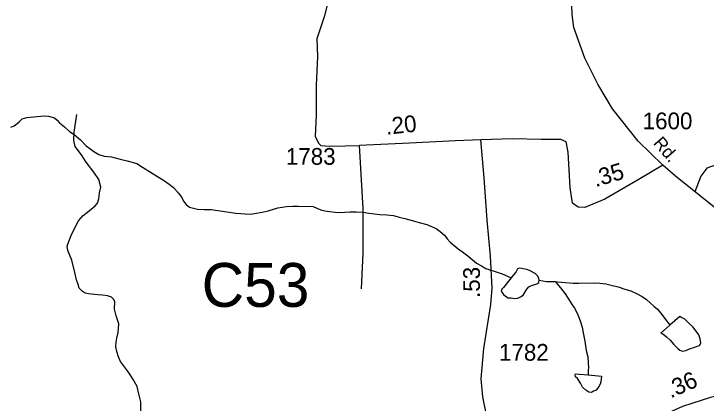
# Model space of a CAD drawing. Extents: x 2001466 to 2224147, y 644118 to 847247.
# Drawn here: x 2024898 to 2030071, y 729712 to 732621 of the extents above; entities that cross this region are included whole.
import ezdxf

# ---------------------------------------------------------------- set-up
doc = ezdxf.new("R2010")
doc.units = 0
for name, color, linetype in [('Exist Hydrographic Misc Water Feature', 7, 'Continuous'), ('Exist Road Non-System Type 51', 7, 'Continuous'), ('Exist Road Secondary Mileage Hundredths English Label', 7, 'Continuous'), ('Exist Road Secondary Structure Culvert Number Label', 7, 'Continuous'), ('Exist Road Secondary Type 51 Attributed', 7, 'Continuous'), ('Exist Road Secondary Type 51 Label', 7, 'Continuous'), ('Exist Road Secondary Type 51 Number Label', 7, 'Continuous')]:
    doc.layers.add(name, color=color, linetype=linetype)

msp = doc.modelspace()

# ---------------------------------------------------------------- linework, layer by layer
at = {"layer": 'Exist Hydrographic Misc Water Feature'}
for points in [[(2024874.8, 731774.2), (2024900.8, 731784.3), (2024922.7, 731802.7), (2024936.9, 731814.7), (2024960.7, 731836.4), (2024994.7, 731847.2), (2025072.6, 731855.4), (2025128.4, 731859.2), (2025156.5, 731857.8), (2025202.4, 731843.8), (2025220.7, 731827.8), (2025238.7, 731806.1), (2025276.9, 731775.8), (2025314.8, 731742.3), (2025349, 731718.6), (2025395.2, 731680.7), (2025437.4, 731634.8), (2025465.7, 731614.5), (2025495.7, 731592.6), (2025533.8, 731571.2), (2025573.8, 731557.3), (2025627.9, 731553.8), (2025691.9, 731536), (2025746, 731521.8), (2025771.9, 731515.5), (2025816.2, 731502.3), (2025858.2, 731476.1), (2025932.4, 731430.3), (2026024.7, 731373.4), (2026058.7, 731347.3), (2026090.9, 731323.6), (2026129.1, 731281), (2026153.3, 731249.4), (2026165.2, 731221.3), (2026185.3, 731195.4), (2026211.5, 731177.6), (2026239.4, 731168), (2026271.4, 731161.6), (2026319.4, 731159.9), (2026371.2, 731158.8), (2026489.5, 731140.8), (2026555.6, 731132.9), (2026593.7, 731129.7), (2026625.9, 731125.7), (2026665.7, 731123.3), (2026695.8, 731130), (2026753.7, 731140.3), (2026797.5, 731150.1), (2026871.6, 731170.7), (2026935.5, 731180.9), (2026983.5, 731184.8), (2027023.5, 731183.2), (2027133.6, 731181.8), (2027161.5, 731169.7), (2027191.9, 731156), (2027221.6, 731149.7), (2027255.6, 731144), (2027297.7, 731139.9), (2027334, 731136.7), (2027371.9, 731138.4), (2027409.6, 731140.9), (2027457.8, 731140.7), (2027507.8, 731138.9), (2027549.7, 731131.5)], [(2027549.7, 731131.5), (2027591.9, 731125.7), (2027633.7, 731121.6), (2027685.8, 731119.7), (2027735.9, 731113.7), (2027775.8, 731102.2), (2027818.3, 731090.7), (2027874.1, 731076.5), (2027926.3, 731063.1), (2027984.2, 731047.2), (2028054.3, 731017.8), (2028084.4, 730995.9), (2028116.4, 730967.4), (2028136.7, 730939.9), (2028158.9, 730915.6), (2028186.8, 730889.6), (2028219, 730864.4), (2028251.2, 730842.4), (2028291.1, 730812), (2028355.5, 730758.3), (2028391.4, 730737), (2028425.7, 730719), (2028509.7, 730691.1), (2028546, 730677.3), (2028585.8, 730661.6), (2028614.1, 730648.8)], [(2028823.9, 730631.4), (2028820, 730644.6), (2028812, 730660.3), (2028791.9, 730680.4), (2028749.6, 730704.2), (2028729.7, 730712), (2028703.9, 730715.8), (2028677.7, 730719.6), (2028661.9, 730715.9), (2028647.7, 730689.9), (2028619.8, 730656), (2028614.1, 730648.8)], [(2028614.1, 730648.8), (2028556.1, 730575.3), (2028544.2, 730563.3), (2028539.9, 730547.7), (2028556.5, 730523.6), (2028572.5, 730511.8), (2028592.6, 730499.9), (2028614.7, 730497.8), (2028638.5, 730494), (2028664.5, 730496), (2028684.6, 730506.2), (2028704.5, 730519.7), (2028718.3, 730544.1), (2028730.4, 730564.4), (2028746.1, 730580.4), (2028766.2, 730592.3), (2028790.2, 730598.4), (2028806.2, 730604.6), (2028820, 730614.2), (2028823.9, 730631.4)], [(2028823.9, 730631.4), (2028878, 730620.4), (2028912, 730620.6), (2028943.2, 730619.9)], [(2028943.2, 730619.9), (2028960, 730618.8), (2029020.1, 730613.4), (2029078.1, 730609.7), (2029118.3, 730608.1), (2029236.2, 730610.6), (2029276.2, 730608.2), (2029320.1, 730604.8), (2029362.1, 730594.9), (2029412.4, 730580.8), (2029464.2, 730564.9), (2029508.5, 730551.8), (2029550.8, 730531.2), (2029592.6, 730509.9), (2029624.8, 730486.3), (2029678.9, 730435.9), (2029707.2, 730414), (2029729.2, 730386.5), (2029755.4, 730354.8), (2029775.5, 730326.5), (2029787.6, 730312.3), (2029799.3, 730294)], [(2028943.2, 730619.9), (2028982.4, 730574.8), (2029016.4, 730529), (2029038.6, 730493.2), (2029065, 730453.4), (2029086.9, 730421.8), (2029105, 730389.4), (2029113, 730372), (2029129.4, 730327.4), (2029143.3, 730279.5), (2029151.7, 730237.5), (2029163.8, 730175.8), (2029174.3, 730105.8), (2029186.4, 730058), (2029188.6, 730012), (2029192.8, 729978.2), (2029188.6, 729957.9), (2029188.6, 729923.4)], [(2029799.3, 730294), (2029733.1, 730235.5), (2029748, 730230.2), (2029773.9, 730208.4), (2029802, 730182.4), (2029830.3, 730150.6), (2029858.1, 730120.6), (2029874.3, 730108.8), (2029894.2, 730101), (2029918.2, 730105.4), (2029954.5, 730119.4), (2029986.1, 730131.1), (2030004.1, 730137.3), (2030020.1, 730143.5), (2030030, 730161.4), (2030025.9, 730193.4), (2030015.6, 730221.5), (2029995.5, 730249), (2029971.7, 730281.5), (2029945.5, 730304.9), (2029925.4, 730325.1), (2029911.5, 730339.3), (2029897.3, 730347), (2029881.3, 730354.7), (2029873.5, 730359), (2029799.3, 730294)], [(2029188.6, 729923.4), (2029288.7, 729914), (2029283, 729872.3), (2029279.3, 729854.3), (2029269.2, 729836.4), (2029259.4, 729821.9), (2029249.3, 729808.1), (2029229.7, 729800.3), (2029213.3, 729791.6), (2029193.6, 729793.7), (2029171.2, 729808.1), (2029147, 729831.6), (2029131, 729861.5), (2029108.9, 729895.5), (2029094.9, 729909.8), (2029090.8, 729921.3), (2029094.7, 729931.9), (2029122.8, 729929.7), (2029188.6, 729923.4)]]:
    msp.add_lwpolyline(points, dxfattribs=at)
at = {"layer": 'Exist Road Non-System Type 51'}
for points in [[(2027277.1, 732833.1), (2027215.7, 732598.7), (2027161.9, 732433.5), (2027165.7, 732299), (2027158.1, 732088.5), (2027158.1, 731861.8), (2027150.4, 731708.1), (2027173.4, 731654.3), (2027191.1, 731637), (2027223.7, 731634.3), (2027265.7, 731632.2), (2027481, 731637.6)], [(2025846, 729639.5), (2025846, 729722.5), (2025832.2, 729782.3), (2025818.4, 729837.6), (2025790.8, 729888.3), (2025764.6, 729928), (2025747.2, 729954.7), (2025717.8, 729993.5), (2025695, 730024.3), (2025679, 730059.1), (2025666.9, 730098), (2025660.2, 730132.8), (2025662.9, 730168.9), (2025666.9, 730197), (2025677.6, 730239.9), (2025681.6, 730304.1), (2025662.8, 730365.2), (2025651, 730413.3), (2025652.2, 730472), (2025642.9, 730489.4), (2025626.8, 730504.1), (2025598.7, 730514.8), (2025561.2, 730518.9), (2025526.5, 730521.5), (2025456.9, 730529.6), (2025431.5, 730534.9), (2025408.7, 730548.3), (2025387.3, 730572.4), (2025378, 730597.8), (2025367.3, 730634.5), (2025352.6, 730689.4), (2025331.1, 730780.4), (2025301.7, 730852.7), (2025297.7, 730886.2), (2025310.7, 730926.5), (2025332.5, 730978), (2025381, 731075.1), (2025415.1, 731113.9), (2025448.8, 731139.7), (2025506.1, 731187.8), (2025524.1, 731206.5), (2025534.2, 731239.3), (2025536.2, 731259.4), (2025538.1, 731284), (2025547.2, 731325.3), (2025533.5, 731382.7), (2025496.8, 731437.8), (2025439.4, 731513.6), (2025402.7, 731568.6), (2025356.8, 731630.6), (2025347.6, 731674.2), (2025349.9, 731736.2), (2025368.3, 731869.4)], [(2032129.8, 731851.1), (2032133, 731610.8), (2032113.6, 731568.6), (2032081.1, 731549.1), (2032022.7, 731539.3), (2031607.3, 731523.1), (2031441.8, 731529.6), (2031350.9, 731532.8), (2031243.8, 731529.6), (2031104.3, 731529.6), (2030195.6, 731510.1), (2030075.6, 731467.9), (2030030.1, 731409.4), (2029986.2, 731292.2)], [(2027496, 730566.8), (2027507.5, 730832), (2027507.5, 731166.3), (2027481, 731637.6)]]:
    msp.add_lwpolyline(points, dxfattribs=at)
at = {"layer": 'Exist Road Secondary Type 51 Attributed'}
for points in [[(2029746.2, 731491.1), (2029563.6, 731670.6), (2029370.5, 731910.5), (2029261.5, 732095.7), (2029164.9, 732291.3), (2029082.9, 732520), (2029070.4, 732615.8), (2029064.8, 732753.5), (2029063.2, 733102.1), (2029074.4, 733807.4), (2029059.1, 734350), (2029052.7, 734762.2), (2029065.6, 735129.3), (2029114.7, 735520.6), (2029163.7, 735775), (2029181, 735907.1)], [(2028388.2, 731679.5), (2028196.7, 731673), (2027853.9, 731655.3), (2027481, 731637.6)], [(2029746.2, 731491.1), (2029575.3, 731388.8), (2029313, 731235.8), (2029163.3, 731174.7), (2029113.5, 731176.3), (2029073.2, 731206.9), (2029055.5, 731324.4), (2029039.4, 731586.9), (2029025.4, 731665), (2028985.9, 731681.1), (2028837.1, 731683.5), (2028626.3, 731686.7), (2028388.2, 731679.5)], [(2028880.7, 729092.3), (2028758.3, 729141.8), (2028648.8, 729211), (2028563.6, 729302.8), (2028494.4, 729428.4), (2028438, 729587.8), (2028401.8, 729758.5), (2028389, 729893.7), (2028409.9, 730120.8), (2028461.8, 730450.1), (2028473, 730572.4), (2028459.8, 730811.6), (2028434, 731080.5), (2028411.1, 731395.3), (2028388.2, 731679.5)], [(2030836.1, 729789.5), (2030758.3, 729898.6), (2030700.4, 730029), (2030657, 730191.6), (2030615.5, 730390.5), (2030563.2, 730634.4), (2030535.9, 730748.8), (2030500.1, 730844.6), (2030455.8, 730906.6), (2030394.7, 730964.5), (2030252.3, 731079.7), (2030006.1, 731276.1), (2029842.8, 731408.1), (2029746.2, 731491.1)], [(2030836.1, 729789.5), (2030587.9, 729812), (2030399.7, 729816.9), (2030289.4, 729800.8), (2030102.8, 729754.1), (2029893.6, 729686.4), (2029711.8, 729605.9), (2029556.5, 729515.7), (2029159.1, 729269.4), (2029016.2, 729175.8)]]:
    msp.add_lwpolyline(points, dxfattribs=at)

# ---------------------------------------------------------------- texts
at = {"layer": 'Exist Road Secondary Mileage Hundredths English Label'}
for s, rotation, p in [('.20', 5.9765, (2027681.6, 731717.6)), ('.35', 16.7047, (2029245, 731325.6)), ('.53', 90, (2028380.4, 730498.1)), ('.36', 23.8834, (2029805.6, 729746.7))]:
    msp.add_text(s, height=125, rotation=rotation, dxfattribs=at).set_placement(p)
at = {"layer": 'Exist Road Secondary Structure Culvert Number Label'}
msp.add_text('C53', height=328.08, dxfattribs=at).set_placement((2026301.8, 730431.4))
at = {"layer": 'Exist Road Secondary Type 51 Label'}
msp.add_text('Rd.', height=95, rotation=310.8052, dxfattribs=at).set_placement((2029670.3, 731652.7))
at = {"layer": 'Exist Road Secondary Type 51 Number Label'}
for s, p in [('1600', (2029596.2, 731758.7)), ('1783', (2026930.5, 731493.5)), ('1782', (2028522.7, 730029.4))]:
    msp.add_text(s, height=125, dxfattribs=at).set_placement(p)

doc.saveas('drawing.dxf')
